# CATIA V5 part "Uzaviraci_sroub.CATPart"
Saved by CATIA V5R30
Part number: Uzaviraci_sroub
Definition: E 2075_8_12_1
Nomenclature: E 2075_8_12_1
Source: Unknown
Description: PART-E 2075_8_12_1-DESC
Bounding box of the stored display mesh (mm): x -6 to 6, y -6 to 6, z -8 to 0
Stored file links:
  E:\Bakalarka\Model\Forma_v7\Uzaviraci_sroub.CATPart
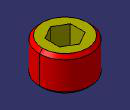
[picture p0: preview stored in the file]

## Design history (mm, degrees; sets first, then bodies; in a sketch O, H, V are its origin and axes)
Body1 "E 2075_8_12" (main body)
  Solid1: solid without history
